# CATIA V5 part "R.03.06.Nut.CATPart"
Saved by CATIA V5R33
Part number: R.03.06.Nut
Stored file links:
  C:\Users\Ryzen5700u\Desktop\robot_cicloidale_singolo\Assieme_robot_cicloidale_singolo\R.03.06.Nut.CATPart

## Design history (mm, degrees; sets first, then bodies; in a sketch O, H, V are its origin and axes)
Body1 "Solid1" (main body)
  Solid1: solid without history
